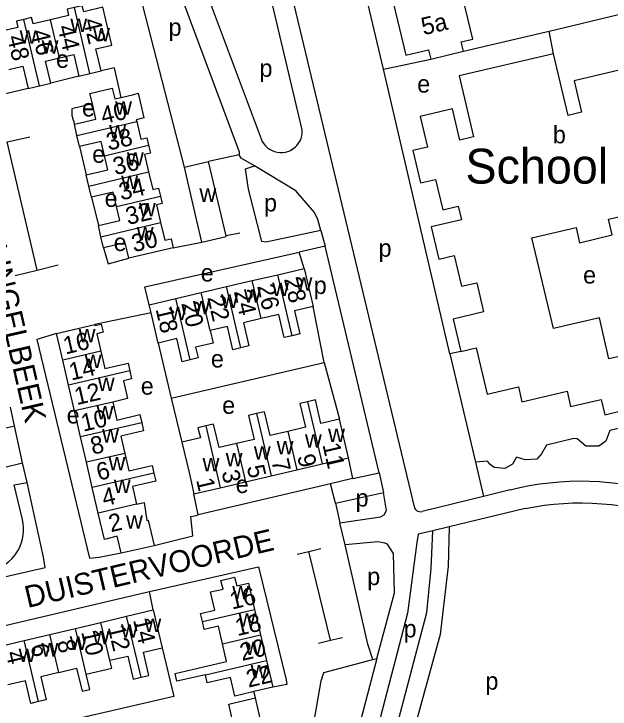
# Model space of a CAD drawing. Extents: x 157646 to 159241, y 379213 to 381217.
# Drawn here: x 158618.3 to 158754.8, y 380820.4 to 380979.6 of the extents above; entities that cross this region are included whole.
import ezdxf

# ---------------------------------------------------------------- set-up
doc = ezdxf.new("R2010")
doc.units = 0
for name, color, linetype in [('BLT_Basislijn', 7, 'Continuous'), ('BLT_Bebouwing', 7, 'Continuous'), ('BLT_Bebouwing_beschrifting', 7, 'Continuous'), ('BLT_Centroide', 7, 'Continuous'), ('BLT_Huisnummer', 7, 'Continuous'), ('BLT_Huisnummer_ tussenligend', 7, 'Continuous'), ('BLT_Onderverdeling_panden', 7, 'Continuous'), ('BLT_Straatnaam', 7, 'Continuous')]:
    doc.layers.add(name, color=color, linetype=linetype)

msp = doc.modelspace()

# ---------------------------------------------------------------- linework, layer by layer
at = {"layer": 'BLT_Basislijn'}
for p, q in [((158702.9, 380966.97), (158693.43, 381007.6)), ((158684.32, 380953.07), (158671.7, 381006.21)), ((158676.31, 381007.2), (158710.04, 380866.43)), ((158657.46, 380997.59), (158675.16, 380950.41)), ((158742.49, 380976.07), (158778.04, 380984.61)), ((158740.84, 380975.68), (158742.49, 380976.07)), ((158741.9, 380970.5), (158740.84, 380975.68)), ((158702.9, 380966.97), (158713.78, 380969.27)), ((158718.12, 380901.72), (158702.9, 380966.97)), ((158633.13, 380965.34), (158626.69, 380963.72)), ((158621.54, 380962.51), (158615.04, 380961.01)), ((158616.75, 380950.28), (158621.94, 380951.44)), ((158623.56, 380920.92), (158616.75, 380950.28)), ((158633.31, 380949.21), (158634.85, 380942.76)), ((158669.86, 380947.31), (158662.86, 380945.78)), ((158636.06, 380937.61), (158637.61, 380931.13)), ((158688.61, 380930), (158689.58, 380926.38)), ((158670.02, 380929.39), (158666.86, 380928.77)), ((158654.78, 380926.05), (158661.33, 380927.35)), ((158689.58, 380926.38), (158683.62, 380925.05)), ((158701.93, 380874.5), (158689.58, 380926.38)), ((158684.77, 380921.29), (158683.62, 380925.05)), ((158623.56, 380920.92), (158628.4, 380922.1)), ((158618.57, 380919.71), (158623.56, 380920.92)), ((158689.33, 380899.76), (158686.8, 380912.59)), ((158649.67, 380911.15), (158636.77, 380908.44)), ((158651.29, 380904.23), (158654.31, 380891.63)), ((158720.63, 380902.29), (158718.12, 380901.72)), ((158718.12, 380901.72), (158723.98, 380876.9)), ((158654.31, 380891.63), (158689.33, 380899.76)), ((158689.33, 380899.76), (158692.86, 380886.8)), ((158654.31, 380891.63), (158656.75, 380881.54)), ((158618.39, 380885.29), (158617.45, 380889.52)), ((158590.4, 380878.53), (158618.39, 380885.29)), ((158620.27, 380876.82), (158618.39, 380885.29)), ((158695.94, 380873.2), (158694.92, 380877.95)), ((158615.92, 380875.75), (158620.27, 380876.82)), ((158621.28, 380872.26), (158620.27, 380876.82)), ((158723.98, 380876.9), (158725.8, 380869.09)), ((158695.94, 380873.2), (158701.93, 380874.5)), ((158701.93, 380874.5), (158702.94, 380870.02)), ((158690.78, 380871.94), (158660.51, 380864.86)), ((158691.9, 380867.51), (158690.78, 380871.94)), ((158731.91, 380870.61), (158725.8, 380869.09)), ((158660.51, 380864.86), (158659.51, 380869.69)), ((158691.9, 380867.51), (158702.94, 380870.02)), ((158725.8, 380869.09), (158711.82, 380865.62)), ((158691.9, 380867.51), (158692.96, 380863.07)), ((158735.41, 380866.29), (158717.95, 380862.12)), ((158694.17, 380858), (158692.96, 380863.07)), ((158717.95, 380862.12), (158714.21, 380861.23)), ((158683.12, 380855.86), (158685.85, 380856.5)), ((158685.85, 380856.5), (158688.59, 380857.14)), ((158690.82, 380836.16), (158685.85, 380856.5)), ((158650.16, 380843.08), (158649.29, 380847.32)), ((158688.07, 380835.51), (158690.82, 380836.16)), ((158690.82, 380836.16), (158693.56, 380836.8)), ((158700.47, 380831.7), (158701.41, 380831.94)), ((158673.59, 380822.95), (158673.22, 380824.39))]:
    msp.add_line(p, q, dxfattribs=at)
for points in [[(158652.91, 380993.49), (158669.86, 380948.05), (158669.86, 380947.31)], [(158657.31, 380944.47), (158645.24, 380991.69)], [(158721.24, 380971.06), (158740.21, 380975.53), (158740.84, 380975.68)], [(158642.8, 380960.5), (158641.31, 380967.26), (158638.26, 380966.54)], [(158636.25, 380959.01), (158631.54, 380957.85), (158631.54, 380956.33), (158632.11, 380954.33)], [(158675.16, 380950.41), (158675.49, 380949.88), (158675.89, 380949.4), (158676.34, 380948.97), (158676.85, 380948.6), (158677.39, 380948.3), (158677.98, 380948.08), (158678.58, 380947.93), (158679.2, 380947.85), (158679.83, 380947.86), (158680.45, 380947.95), (158681.05, 380948.11), (158681.62, 380948.36), (158682.16, 380948.67), (158682.66, 380949.05), (158683.1, 380949.49), (158683.49, 380949.98), (158683.81, 380950.52), (158684.05, 380951.09), (158684.22, 380951.69), (158684.32, 380952.31), (158684.33, 380952.93), (158684.32, 380953.07)], [(158673.36, 380944.81), (158670.32, 380946.6), (158669.86, 380947.31)], [(158688.61, 380930), (158675.99, 380927.32), (158675.03, 380927.51), (158671.98, 380939.5), (158671.34, 380944.12), (158673.36, 380944.81)], [(158688.61, 380930), (158687.92, 380932.54), (158687.12, 380934.13), (158682.83, 380939.06), (158673.36, 380944.81)], [(158638.82, 380926.02), (158639.84, 380922.4), (158644.58, 380923.65)], [(158649.24, 380913), (158648.22, 380917.13), (158683.62, 380925.05)], [(158628.02, 380906.41), (158623.5, 380905), (158635.57, 380854.95), (158637.8, 380855.14), (158642.84, 380856.15)], [(158769.12, 380887.54), (158754.8, 380884.17), (158753.88, 380881.78), (158752.24, 380880.62), (158749.27, 380880.57), (158747.29, 380882.27), (158746.53, 380882.34), (158740.26, 380880.8), (158739.15, 380878.84), (158738.04, 380877.65), (158735.36, 380877.49), (158733.42, 380878.06), (158732.47, 380876.47), (158730.72, 380875.5), (158728.25, 380875.69), (158727.05, 380876.65), (158726.85, 380877.14), (158723.98, 380876.9)], [(158593.4, 380865.68), (158593.54, 380865.08), (158598.14, 380847.01), (158598.43, 380846.64), (158625.39, 380852.83), (158625.07, 380855.21), (158621.28, 380872.26)], [(158620.2, 380863.83), (158618.31, 380871.73), (158621.28, 380872.26)], [(158695.94, 380873.2), (158695.52, 380873.11), (158690.78, 380871.94)], [(158731.91, 380870.61), (158734.14, 380871.13), (158736.39, 380871.58), (158738.65, 380871.95), (158740.92, 380872.24), (158743.21, 380872.45), (158745.5, 380872.58), (158747.79, 380872.63), (158750.08, 380872.6), (158752.37, 380872.49), (158754.65, 380872.3), (158756.93, 380872.03), (158758.44, 380871.81)], [(158692.96, 380863.07), (158702.22, 380864.38), (158703.08, 380864.91), (158703.62, 380865.86), (158702.94, 380870.02)], [(158735.41, 380866.29), (158737.57, 380866.71), (158739.75, 380867.05), (158741.93, 380867.32), (158744.13, 380867.5), (158746.33, 380867.6), (158748.54, 380867.63), (158750.74, 380867.57), (158752.94, 380867.43), (158755.13, 380867.22), (158757.32, 380866.92), (158757.65, 380866.87)], [(158710.04, 380866.43), (158710.24, 380866.13), (158710.5, 380865.89), (158710.8, 380865.71), (158711.14, 380865.6), (158711.49, 380865.57), (158711.82, 380865.62)], [(158650.41, 380857.84), (158659.28, 380860.05), (158658.78, 380864.47), (158660.07, 380864.75), (158660.51, 380864.86)], [(158616.44, 380853.62), (158617.13, 380854.16), (158617.77, 380854.77), (158618.35, 380855.43), (158618.87, 380856.14), (158619.32, 380856.89), (158619.71, 380857.68), (158620.02, 380858.51), (158620.25, 380859.36), (158620.4, 380860.22), (158620.48, 380861.1), (158620.47, 380861.98), (158620.39, 380862.86), (158620.23, 380863.72), (158620.2, 380863.83)], [(158710.58, 380858.54), (158708.44, 380842.33), (158697.05, 380798.64), (158700.23, 380797.78), (158701.12, 380798), (158701.28, 380798.48), (158712.85, 380842.49), (158713.82, 380852.58), (158714.21, 380861.23)], [(158717.95, 380862.12), (158717.75, 380853.11), (158715.92, 380837.46), (158705.74, 380800.48), (158705.04, 380796.98), (158705.45, 380796.57), (158750.2, 380784.71)], [(158714.21, 380861.23), (158710.89, 380860.43), (158710.58, 380858.54)], [(158701.41, 380831.94), (158705.46, 380846.97), (158705.23, 380855.98), (158703.87, 380858.16), (158703.24, 380858.42), (158701.6, 380858.71), (158694.17, 380858)], [(158700.47, 380831.7), (158699.36, 380835.22), (158694.17, 380858)], [(158649.29, 380847.32), (158674.33, 380852.99), (158680.64, 380827.1), (158680.79, 380825.99), (158677.55, 380825.4)], [(158600.92, 380835.93), (158648.65, 380847.17), (158649.29, 380847.32)], [(158652.22, 380834.4), (158654.9, 380823.3), (158606.54, 380812.09)], [(158701.41, 380831.94), (158693.37, 380801.34), (158692.77, 380799.88), (158684.64, 380802.71), (158683.96, 380803.96), (158683.06, 380808.79)], [(158683.06, 380808.79), (158685.72, 380810.11), (158688.68, 380826.88), (158689.29, 380828.79), (158700.47, 380831.7)]]:
    msp.add_lwpolyline(points, dxfattribs=at)
at = {"layer": 'BLT_Bebouwing'}
for p, q in [((158713.78, 380969.27), (158721.24, 380971.06)), ((158635.69, 380965.94), (158638.26, 380966.54)), ((158633.13, 380965.34), (158635.69, 380965.94)), ((158621.54, 380962.51), (158624.12, 380963.11)), ((158624.12, 380963.11), (158626.69, 380963.72)), ((158632.71, 380951.77), (158632.11, 380954.33)), ((158633.31, 380949.21), (158632.71, 380951.77)), ((158666.86, 380928.77), (158662.86, 380945.78)), ((158635.45, 380940.19), (158634.85, 380942.76)), ((158636.06, 380937.61), (158635.45, 380940.19)), ((158638.21, 380928.58), (158637.61, 380931.13)), ((158638.82, 380926.02), (158638.21, 380928.58)), ((158654.78, 380926.05), (158644.58, 380923.65)), ((158678.72, 380919.88), (158684.77, 380921.29)), ((158684.77, 380921.29), (158686.8, 380912.59)), ((158666.99, 380917.14), (158672.88, 380918.51)), ((158672.88, 380918.51), (158678.72, 380919.88)), ((158661.17, 380915.78), (158666.99, 380917.14)), ((158655.34, 380914.42), (158661.17, 380915.78)), ((158649.24, 380913), (158655.34, 380914.42)), ((158649.67, 380911.15), (158649.24, 380913)), ((158628.02, 380906.41), (158636.77, 380908.44)), ((158629.44, 380900.33), (158628.02, 380906.41)), ((158630.78, 380894.56), (158629.44, 380900.33)), ((158632.15, 380888.67), (158630.78, 380894.56)), ((158633.53, 380882.72), (158632.15, 380888.67)), ((158694.92, 380877.95), (158692.86, 380886.8)), ((158634.88, 380876.91), (158633.53, 380882.72)), ((158688.87, 380876.53), (158694.92, 380877.95)), ((158636.22, 380871.13), (158634.88, 380876.91)), ((158683.05, 380875.18), (158688.87, 380876.53)), ((158671.33, 380872.45), (158677.19, 380873.81)), ((158677.19, 380873.81), (158683.05, 380875.18)), ((158665.52, 380871.09), (158671.33, 380872.45)), ((158637.58, 380865.28), (158636.22, 380871.13)), ((158659.51, 380869.69), (158665.52, 380871.09)), ((158642.84, 380856.15), (158650.41, 380857.84)), ((158644.09, 380841.64), (158650.16, 380843.08)), ((158673.4, 380843.19), (158674.76, 380837.35)), ((158638.2, 380840.25), (158644.09, 380841.64)), ((158626.47, 380837.48), (158632.35, 380838.86)), ((158632.35, 380838.86), (158638.2, 380840.25)), ((158620.61, 380836.09), (158626.47, 380837.48)), ((158674.76, 380837.35), (158676.13, 380831.49)), ((158614.81, 380834.72), (158620.61, 380836.09)), ((158676.13, 380831.49), (158677.55, 380825.4)), ((158677.55, 380825.4), (158673.22, 380824.39)), ((158676.9, 380808.64), (158673.59, 380822.95))]:
    msp.add_line(p, q, dxfattribs=at)
for points in [[(158728.8, 381007.75), (158719.94, 381005.62), (158720.4, 381003.68), (158714.36, 381002.23), (158713.83, 381004.44), (158705.8, 381002.51), (158706.31, 381000.4), (158701.08, 380999.14), (158703.34, 380989.73), (158701.18, 380989.21), (158702.98, 380981.73), (158705.11, 380982.24), (158708.01, 380970.16), (158713.27, 380971.42), (158713.78, 380969.27)], [(158721.24, 380971.06), (158720.72, 380973.2), (158723.41, 380973.84), (158719.53, 380990.02), (158723.39, 380990.95), (158724.65, 380985.7), (158733.55, 380987.84), (158732.45, 380992.43), (158733.78, 380992.75), (158731.21, 381003.46), (158729.9, 381003.15), (158728.8, 381007.75)], [(158632.13, 380981.07), (158630.43, 380980.67), (158630.77, 380979.25), (158626.67, 380978.29)], [(158638.26, 380966.54), (158637.07, 380971.58), (158640.67, 380972.42), (158638.62, 380981.13), (158634.27, 380980.11), (158633.94, 380981.49), (158632.13, 380981.07)], [(158620.54, 380978.34), (158618.83, 380977.94), (158619.16, 380976.52), (158615.05, 380975.55)], [(158626.67, 380978.29), (158622.67, 380977.35), (158622.33, 380978.77), (158620.54, 380978.34)], [(158626.69, 380963.72), (158625.5, 380968.79), (158628.73, 380969.55)], [(158628.73, 380969.55), (158631.96, 380970.31), (158633.13, 380965.34)], [(158741.9, 380970.5), (158720.23, 380965.4), (158723.52, 380951.44), (158720.44, 380950.72), (158718.75, 380957.88), (158711.36, 380956.14)], [(158757.25, 380966.83), (158746.57, 380964.32), (158748.28, 380957.07), (158745.23, 380956.35), (158741.9, 380970.5)], [(158617.09, 380966.86), (158620.34, 380967.63), (158621.54, 380962.51)], [(158736.9, 380928.32), (158747.03, 380930.71), (158747.85, 380927.21), (158755.32, 380928.97), (158754.47, 380932.58), (158761.46, 380934.23), (158760.64, 380937.69), (158767.61, 380939.33), (158766.76, 380942.93), (158773.81, 380944.59), (158771.82, 380953.02), (158764.59, 380951.32), (158762.4, 380960.61), (158758.9, 380959.79), (158757.25, 380966.83)], [(158636.25, 380959.01), (158635.68, 380961.41), (158640.78, 380962.61), (158641.35, 380960.18), (158642.8, 380960.5)], [(158642.8, 380960.5), (158645.73, 380961.14), (158646.72, 380961.44)], [(158646.72, 380961.44), (158648.05, 380955.78), (158646.3, 380955.37), (158646.4, 380954.99)], [(158632.11, 380954.33), (158637.07, 380955.5), (158636.25, 380959.01)], [(158646.4, 380954.99), (158647.35, 380950.93), (158648.7, 380951.24), (158649.1, 380949.52)], [(158711.36, 380956.14), (158713.01, 380949.1), (158709.65, 380948.31), (158711.39, 380940.91), (158714.87, 380941.72), (158716.51, 380934.74), (158720.05, 380935.58), (158720.79, 380932.46), (158713.86, 380930.83), (158715.61, 380923.43), (158719.15, 380924.26), (158720.81, 380917.23), (158724.3, 380918.05), (158725.87, 380911.36), (158718.88, 380909.72), (158720.63, 380902.29)], [(158638.99, 380947.14), (158638.23, 380950.36), (158633.31, 380949.21)], [(158649.1, 380949.52), (158649.53, 380947.7), (158648.2, 380947.39), (158649.13, 380943.41)], [(158634.85, 380942.76), (158639.75, 380943.92), (158638.99, 380947.14)], [(158657.31, 380944.47), (158657.99, 380944.63), (158662.86, 380945.78)], [(158661.33, 380927.35), (158660.19, 380932.22), (158657.31, 380944.47)], [(158649.13, 380943.41), (158650.08, 380939.39), (158651.42, 380939.7), (158651.84, 380937.9)], [(158641.73, 380935.52), (158640.97, 380938.77), (158636.06, 380937.61)], [(158651.84, 380937.9), (158652.24, 380936.19), (158650.92, 380935.88), (158651.88, 380931.8)], [(158637.61, 380931.13), (158642.5, 380932.28), (158641.73, 380935.52)], [(158651.88, 380931.8), (158652.84, 380927.75), (158654.3, 380928.09), (158654.78, 380926.05)], [(158661.33, 380927.35), (158666.89, 380928.66), (158666.86, 380928.77)], [(158741.85, 380907.52), (158736.9, 380928.32)], [(158644.58, 380923.65), (158643.75, 380927.18), (158638.82, 380926.02)], [(158686.8, 380912.59), (158682.55, 380911.6), (158683.77, 380906.33), (158681.98, 380905.91)], [(158651.29, 380904.23), (158650.37, 380908.15), (158649.67, 380911.15)], [(158681.98, 380905.91), (158680.19, 380905.49), (158678.96, 380910.77), (158674.9, 380909.83)], [(158674.9, 380909.83), (158670.85, 380908.88), (158672.1, 380903.55), (158670.26, 380903.13)], [(158720.63, 380902.29), (158724.19, 380903.13), (158726.7, 380892.5), (158733.82, 380894.18), (158734.62, 380890.75), (158744.96, 380893.18), (158745.78, 380889.66), (158752.8, 380891.32), (158753.63, 380887.81), (158761.12, 380889.58), (158758.33, 380901.46), (158754.58, 380900.58), (158752.37, 380909.99), (158741.85, 380907.52)], [(158636.77, 380908.44), (158636.82, 380908.21), (158638.26, 380908.55), (158638.69, 380906.69), (158637.25, 380906.36), (158638.18, 380902.36)], [(158670.26, 380903.13), (158668.43, 380902.7), (158667.19, 380908.02), (158663.19, 380907.09)], [(158663.19, 380907.09), (158663.88, 380904.21), (158659.87, 380903.28), (158660.44, 380900.81), (158658.62, 380900.38)], [(158658.62, 380900.38), (158656.79, 380899.95), (158655.56, 380905.23), (158651.29, 380904.23)], [(158638.18, 380902.36), (158639.11, 380898.37), (158644.42, 380899.61), (158644.83, 380897.82)], [(158644.83, 380897.82), (158645.24, 380896.04), (158643.36, 380895.6), (158644.32, 380891.5), (158640.91, 380890.7)], [(158640.91, 380890.7), (158641.86, 380886.59), (158647.13, 380887.82), (158647.55, 380885.98)], [(158685.55, 380890.76), (158683.77, 380890.35), (158685.03, 380884.92), (158681, 380883.98)], [(158692.86, 380886.8), (158688.58, 380885.8), (158687.33, 380891.18), (158685.55, 380890.76)], [(158681, 380883.98), (158676.96, 380883.04), (158675.7, 380888.48), (158673.87, 380888.05)], [(158673.87, 380888.05), (158672.04, 380887.62), (158673.31, 380882.16), (158669.29, 380881.22)], [(158647.55, 380885.98), (158647.98, 380884.15), (158642.76, 380882.93), (158643.68, 380878.96)], [(158662.22, 380885.25), (158660.43, 380884.83), (158660.97, 380882.52), (158656.75, 380881.54)], [(158669.29, 380881.22), (158665.26, 380880.29), (158664.01, 380885.67), (158662.22, 380885.25)], [(158656.75, 380881.54), (158658.38, 380874.56), (158659.51, 380869.69)], [(158643.68, 380878.96), (158644.61, 380874.98), (158649.91, 380876.21), (158650.33, 380874.4)], [(158650.33, 380874.4), (158650.75, 380872.6), (158645.42, 380871.36), (158646.36, 380867.32)], [(158646.36, 380867.32), (158648.11, 380867.72), (158648.75, 380863.61), (158649.05, 380863.68), (158650.41, 380857.84)], [(158642.84, 380856.15), (158641.95, 380859.95), (158638.98, 380859.25), (158637.58, 380865.28)], [(158661.44, 380840.41), (158661.02, 380842.24), (158664.28, 380843), (158663.3, 380847.22), (158666.17, 380847.88), (158665.7, 380849.85), (158668.83, 380850.59), (158669.3, 380848.61), (158672, 380849.24), (158673.4, 380843.19)], [(158650.16, 380843.08), (158651.32, 380838.21), (158652.22, 380834.4)], [(158666.07, 380835.33), (158665.13, 380839.35), (158661.87, 380838.59), (158661.44, 380840.41)], [(158647.39, 380827.67), (158649.2, 380828.1), (158647.94, 380833.39), (158652.22, 380834.4)], [(158662.12, 380828.23), (158655.59, 380826.8), (158655.18, 380828.56), (158661.69, 380830.07), (158667, 380831.31), (158666.07, 380835.33)], [(158640.26, 380831.57), (158644.34, 380832.53), (158645.59, 380827.24), (158647.39, 380827.67)], [(158634.83, 380828.37), (158640.69, 380829.76), (158640.26, 380831.57)], [(158628.54, 380828.76), (158632.64, 380829.73), (158633.88, 380824.47), (158635.66, 380824.89), (158634.83, 380828.37)], [(158628.54, 380828.76), (158624.44, 380827.79), (158625.69, 380822.49), (158623.92, 380822.08)], [(158673.22, 380824.39), (158672.68, 380824.26), (158668.86, 380823.37), (158667.87, 380827.63), (158662.54, 380826.39), (158662.12, 380828.23)], [(158623.92, 380822.08), (158622.15, 380821.66), (158620.91, 380826.87), (158616.89, 380825.92)], [(158668.83, 380815.81), (158667.48, 380821.53), (158668.72, 380821.82), (158673.59, 380822.95)]]:
    msp.add_lwpolyline(points, dxfattribs=at)
at = {"layer": 'BLT_Onderverdeling_panden'}
for p, q in [((158635.69, 380965.94), (158632.13, 380981.07)), ((158624.12, 380963.11), (158620.54, 380978.34)), ((158628.73, 380969.55), (158626.67, 380978.29)), ((158632.71, 380951.77), (158646.4, 380954.99)), ((158638.99, 380947.14), (158649.1, 380949.52)), ((158635.45, 380940.19), (158649.13, 380943.41)), ((158641.73, 380935.52), (158651.84, 380937.9)), ((158638.21, 380928.58), (158651.88, 380931.8)), ((158674.9, 380909.83), (158672.88, 380918.51)), ((158681.98, 380905.91), (158678.72, 380919.88)), ((158670.26, 380903.13), (158666.99, 380917.14)), ((158663.19, 380907.09), (158661.17, 380915.78)), ((158658.62, 380900.38), (158655.34, 380914.42)), ((158638.18, 380902.36), (158629.44, 380900.33)), ((158644.83, 380897.82), (158630.78, 380894.56)), ((158640.91, 380890.7), (158632.15, 380888.67)), ((158685.55, 380890.76), (158688.87, 380876.53)), ((158673.87, 380888.05), (158677.19, 380873.81)), ((158647.55, 380885.98), (158633.53, 380882.72)), ((158662.22, 380885.25), (158665.52, 380871.09)), ((158681, 380883.98), (158683.05, 380875.18)), ((158669.29, 380881.22), (158671.33, 380872.45)), ((158643.68, 380878.96), (158634.88, 380876.91)), ((158650.33, 380874.4), (158636.22, 380871.13)), ((158646.36, 380867.32), (158637.58, 380865.28)), ((158661.44, 380840.41), (158673.4, 380843.19)), ((158647.39, 380827.67), (158644.09, 380841.64)), ((158634.83, 380828.37), (158632.35, 380838.86)), ((158640.26, 380831.57), (158638.2, 380840.25)), ((158628.54, 380828.76), (158626.47, 380837.48)), ((158666.07, 380835.33), (158674.76, 380837.35)), ((158623.92, 380822.08), (158620.61, 380836.09)), ((158662.12, 380828.23), (158676.13, 380831.49))]:
    msp.add_line(p, q, dxfattribs=at)

# ---------------------------------------------------------------- texts
at = {"layer": 'BLT_Bebouwing_beschrifting'}
msp.add_text('School', height=8, dxfattribs=at).set_placement((158721.69, 380940.74))
at = {"layer": 'BLT_Centroide'}
for s, p in [('w', (158631.19, 380975.48)), ('p', (158653.69, 380974.58)), ('w', (158619.58, 380972.78)), ('w', (158636.41, 380973.34)), ('w', (158624.62, 380970.52)), ('e', (158627.92, 380967.27)), ('p', (158674.52, 380965.19)), ('e', (158710.65, 380961.59)), ('e', (158633.87, 380956.13)), ('w', (158641.45, 380956.5)), ('w', (158640.09, 380951.06)), ('b', (158741.73, 380949.97)), ('e', (158636.2, 380945.51)), ('w', (158644.16, 380944.84)), ('w', (158642.84, 380939.47)), ('w', (158660.76, 380936.56)), ('e', (158639.05, 380935.4)), ('p', (158675.56, 380934.37)), ('w', (158646.91, 380933.25)), ('w', (158646.41, 380927.72)), ('e', (158641.12, 380925.3)), ('p', (158701.8, 380923.99)), ('e', (158661.06, 380918.31)), ('e', (158748.65, 380917.84)), ('w', (158682.77, 380916.23)), ('p', (158686.95, 380915.46)), ('w', (158677.42, 380914.98)), ('w', (158665.72, 380912.27)), ('w', (158670.95, 380913.48)), ('w', (158659.27, 380910.77)), ('w', (158653.92, 380909.47)), ('w', (158633.1, 380904.38)), ('w', (158634.48, 380898.47)), ('e', (158663.39, 380898.62)), ('w', (158637.49, 380893.25)), ('e', (158647.33, 380892.4)), ('w', (158637.22, 380886.72)), ('e', (158665.98, 380888)), ('e', (158630.35, 380885.8)), ('w', (158638.47, 380881.44)), ('w', (158684.94, 380880.27)), ('w', (158690.23, 380881.52)), ('w', (158678.45, 380878.73)), ('w', (158673.23, 380877.53)), ('w', (158666.78, 380876)), ('w', (158639.95, 380875.03)), ('w', (158661.48, 380874.8)), ('w', (158641.14, 380869.84)), ('e', (158669.08, 380869.87)), ('p', (158696.53, 380866.76)), ('w', (158643.95, 380861.72)), ('p', (158699.2, 380848.78)), ('w', (158668.29, 380845.5)), ('w', (158669.73, 380839.25)), ('w', (158648.16, 380838.02)), ('w', (158642.8, 380836.75)), ('p', (158707.53, 380836.8)), ('w', (158636.3, 380835.22)), ('w', (158631.06, 380833.95)), ('w', (158671.24, 380832.78)), ('w', (158619.36, 380831.14)), ('w', (158624.58, 380832.42)), ('w', (158672.49, 380827.44)), ('p', (158726.27, 380824.83))]:
    msp.add_text(s, height=4, dxfattribs=at).set_placement(p)
at = {"layer": 'BLT_Huisnummer'}
for s, rotation, p in [('5a', 13.4455, (158712.1, 380974.7)), ('42', 283.2405, (158634.13, 380978.16)), ('46', 283.2438, (158622.3, 380975.57)), ('40', 13.2456, (158638.67, 380954.3)), ('34', 13.2515, (158642.83, 380936.87)), ('30', 13.2471, (158645.72, 380925.01)), ('28', 283.1203, (158680.11, 380918.91)), ('22', 283.1269, (158662.55, 380914.67)), ('18', 283.1312, (158650.71, 380911.97)), ('16', 13.0814, (158630.06, 380901.6)), ('10', 13.0814, (158634.14, 380883.9)), ('11', 283.1167, (158688.92, 380880.94)), ('6', 13.0814, (158637.67, 380872.68)), ('5', 283.1171, (158671.58, 380875.86)), ('1', 283.1191, (158659.98, 380872.88)), ('2', 13.0814, (158640.47, 380860.87)), ('16', 13.0859, (158668.22, 380843.17)), ('14', 283.3071, (158645.54, 380840.81)), ('10', 283.3071, (158633.65, 380838.08)), ('6', 283.3071, (158622.02, 380834.91)), ('22', 13.0994, (158671.98, 380825.28))]:
    msp.add_text(s, height=4, rotation=rotation, dxfattribs=at).set_placement(p)
at = {"layer": 'BLT_Huisnummer_ tussenligend'}
for s, rotation, p in [('44', 283.2405, (158628.2, 380976.65)), ('48', 283.2438, (158616.68, 380974.34)), ('38', 13.2515, (158639.95, 380948.29)), ('36', 13.2515, (158641.46, 380942.66)), ('32', 13.2471, (158644.37, 380931.25)), ('26', 283.1269, (158673.95, 380917.27)), ('24', 283.1269, (158668.63, 380916.05)), ('20', 283.1312, (158656.57, 380913.33)), ('14', 13.0814, (158631.4, 380895.62)), ('12', 13.0814, (158632.63, 380889.99)), ('8', 13.0814, (158636.31, 380878.62)), ('9', 283.1171, (158683.14, 380878.3)), ('7', 283.1171, (158677.21, 380877.24)), ('3', 283.1191, (158665.81, 380874.69)), ('4', 13.0814, (158638.94, 380866.8)), ('18', 13.0859, (158669.45, 380837.08)), ('12', 283.3071, (158639.74, 380839.13)), ('8', 283.3071, (158628.1, 380835.82)), ('20', 13.0859, (158670.53, 380831.39)), ('4', 283.3071, (158616.36, 380833.26))]:
    msp.add_text(s, height=4, rotation=rotation, dxfattribs=at).set_placement(p)
at = {"layer": 'BLT_Straatnaam'}
for s, rotation, p in [('KLINGELBEEK', 282.8584, (158610.63, 380930.58)), ('DUISTERVOORDE', 13.2256, (158621.39, 380843.52))]:
    msp.add_text(s, height=4.9999, rotation=rotation, dxfattribs=at).set_placement(p)

doc.saveas('drawing.dxf')
